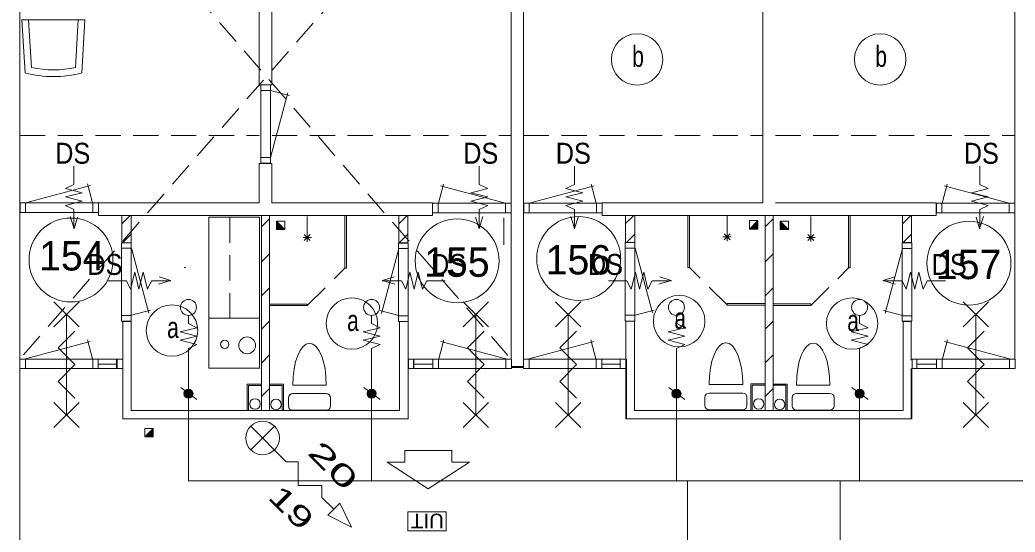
# Model space of a CAD drawing. Extents: x 295824 to 414724, y 24924 to 109024.
# Drawn here: x 302089 to 313944, y 70117 to 76222 of the extents above; entities that cross this region are included whole.
import ezdxf
from ezdxf.enums import TextEntityAlignment as Align

# ---------------------------------------------------------------- set-up
doc = ezdxf.new("R2010")
doc.units = 0
doc.header["$LTSCALE"] = 100
doc.linetypes.add('MEDIUM_DASHED', pattern=[4.5, 3, -1.5])
for name, color, linetype, lineweight in [('1', 7, 'Continuous', 13), ('16', 7, 'Continuous', 13), ('24', 7, 'Continuous', 13), ('61', 7, 'Continuous', 13)]:
    doc.layers.add(name, color=color, linetype=linetype, lineweight=lineweight)

msp = doc.modelspace()

# ---------------------------------------------------------------- hatches: boundary and pattern name
at = {"layer": '24'}
for points in [[(304151.5, 71768.1, 1), (304042.9, 71768.1, 1)], [(306333.5, 71768.1, 1), (306224.9, 71768.1, 1)], [(309964.5, 71768.1, 1), (309855.9, 71768.1, 1)], [(312146.5, 71768.1, 1), (312037.9, 71768.1, 1)]]:
    msp.add_hatch(color=256, dxfattribs=at).paths.add_polyline_path(points)
at = {"layer": '61'}
for points in [[(305244.4, 73722.8), (305144.4, 73822.8), (305144.4, 73722.8)], [(310781.4, 73729.4), (310881.4, 73829.4), (310881.4, 73729.4)], [(311243.8, 73724.1), (311143.8, 73824.1), (311143.8, 73724.1)], [(303578.3, 71252.8), (303678.3, 71352.8), (303678.3, 71252.8)]]:
    msp.add_hatch(color=256, dxfattribs=at).paths.add_polyline_path(points)

# ---------------------------------------------------------------- linework, layer by layer
at = {"layer": '1'}
for p, q in [((304097.2, 71736.8), (304097.2, 70726.3)), ((306279.2, 71730.1), (306279.2, 70726.3)), ((309910.2, 71736.8), (309910.2, 70726.3)), ((312092.2, 71730.1), (312092.2, 70726.3)), ((310043.5, 69843.4), (310043.5, 70726.3)), ((311859, 69838.4), (311859, 70726.3))]:
    msp.add_line(p, q, dxfattribs=at)
at = {"layer": '16'}
for p, q in [((302631.4, 74111.7), (302831.4, 74161.7)), ((307661.7, 74111.7), (307461.7, 74161.7)), ((308594.4, 74111.7), (308794.4, 74161.7)), ((313624.7, 74111.7), (313424.7, 74161.7)), ((303507.8, 73013.5), (303457.8, 73213.5)), ((306785.3, 73013.5), (306835.3, 73213.5)), ((309470.8, 73013.5), (309420.8, 73213.5)), ((312748.2, 73013.5), (312798.2, 73213.5))]:
    msp.add_line(p, q, dxfattribs=at)
at = {"layer": '24'}
for p, q in [((302734.8, 73736.3), (302689.8, 73880.4)), ((302777.2, 73872.1), (302734.8, 73736.3)), ((307515.9, 73872.1), (307558.3, 73736.3)), ((307558.3, 73736.3), (307603.3, 73880.4)), ((308697.7, 73736.3), (308652.7, 73880.4)), ((308740.2, 73872.1), (308697.7, 73736.3)), ((313478.9, 73872.1), (313521.3, 73736.3)), ((313521.3, 73736.3), (313566.3, 73880.4)), ((303747.4, 73159.3), (303883.2, 73116.9)), ((306545.7, 73159.3), (306409.9, 73116.9)), ((309710.4, 73159.3), (309846.2, 73116.9)), ((312508.6, 73159.3), (312372.8, 73116.9)), ((303883.2, 73116.9), (303739, 73071.9)), ((306409.9, 73116.9), (306554, 73071.9)), ((309846.2, 73116.9), (309702, 73071.9)), ((312372.8, 73116.9), (312517, 73071.9)), ((304097.2, 72253.5), (304097.2, 71714.1)), ((306279.2, 72253.5), (306279.2, 71745.1)), ((309910.2, 72253.5), (309910.2, 71714.1)), ((312092.2, 72253.5), (312092.2, 71745.1)), ((304005.6, 71838.9), (304197.1, 71697.3)), ((306187.6, 71838.9), (306379.1, 71697.3)), ((309818.6, 71838.9), (310010.2, 71697.3)), ((312000.6, 71838.9), (312192.1, 71697.3)), ((304097.2, 70726.3), (328693.9, 70726.3))]:
    msp.add_line(p, q, dxfattribs=at)
for points in [[(302831.4, 74161.7), (302631.4, 74211.7), (302731.4, 74261.7), (302731.4, 74480.4)], [(307461.7, 74161.7), (307661.7, 74211.7), (307561.7, 74261.7), (307561.7, 74480.4)], [(308794.4, 74161.7), (308594.4, 74211.7), (308694.4, 74261.7), (308694.4, 74480.4)], [(313424.7, 74161.7), (313624.7, 74211.7), (313524.7, 74261.7), (313524.7, 74480.4)], [(302731.4, 73730.4), (302731.4, 73961.7), (302631.4, 74011.7), (302831.4, 74061.7), (302631.4, 74111.7)], [(307561.7, 73730.4), (307561.7, 73961.7), (307661.7, 74011.7), (307461.7, 74061.7), (307661.7, 74111.7)], [(308694.4, 73730.4), (308694.4, 73961.7), (308594.4, 74011.7), (308794.4, 74061.7), (308594.4, 74111.7)], [(313524.7, 73730.4), (313524.7, 73961.7), (313624.7, 74011.7), (313424.7, 74061.7), (313624.7, 74111.7)], [(303457.8, 73213.5), (303407.8, 73013.5), (303357.8, 73113.5), (303139.1, 73113.5)], [(303889.1, 73113.5), (303657.8, 73113.5), (303607.8, 73013.5), (303557.8, 73213.5), (303507.8, 73013.5)], [(306404, 73113.5), (306635.3, 73113.5), (306685.3, 73013.5), (306735.3, 73213.5), (306785.3, 73013.5)], [(306835.3, 73213.5), (306885.3, 73013.5), (306935.3, 73113.5), (307154, 73113.5)], [(309420.8, 73213.5), (309370.8, 73013.5), (309320.8, 73113.5), (309102, 73113.5)], [(309852, 73113.5), (309620.8, 73113.5), (309570.8, 73013.5), (309520.8, 73213.5), (309470.8, 73013.5)], [(312367, 73113.5), (312598.2, 73113.5), (312648.2, 73013.5), (312698.2, 73213.5), (312748.2, 73013.5)], [(312798.2, 73213.5), (312848.2, 73013.5), (312898.2, 73113.5), (313117, 73113.5)], [(304097.2, 72703.5), (304097.2, 72603.5), (304197.2, 72553.5), (303997.2, 72503.5), (304197.2, 72453.5), (303997.2, 72403.5), (304197.2, 72353.5), (304097.2, 72303.5), (304097.2, 72253.5)], [(306279.2, 72703.5), (306279.2, 72603.5), (306379.2, 72553.5), (306179.2, 72503.5), (306379.2, 72453.5), (306179.2, 72403.5), (306379.2, 72353.5), (306279.2, 72303.5), (306279.2, 72253.5)], [(309910.2, 72703.5), (309910.2, 72603.5), (310010.2, 72553.5), (309810.2, 72503.5), (310010.2, 72453.5), (309810.2, 72403.5), (310010.2, 72353.5), (309910.2, 72303.5), (309910.2, 72253.5)], [(312092.2, 72703.5), (312092.2, 72603.5), (312192.2, 72553.5), (311992.2, 72503.5), (312192.2, 72453.5), (311992.2, 72403.5), (312192.2, 72353.5), (312092.2, 72303.5), (312092.2, 72253.5)]]:
    msp.add_lwpolyline(points, dxfattribs=at)
for centre, radius in [((304097.2, 72795.2), 95), ((306279.2, 72795.2), 95), ((309910.2, 72795.2), 95), ((312092.2, 72795.2), 95), ((304097.2, 71768.1), 54.3), ((306279.2, 71768.1), 54.3), ((309910.2, 71768.1), 54.3), ((312092.2, 71768.1), 54.3)]:
    msp.add_circle(centre, radius, dxfattribs=at)
at = {"layer": '61'}
for p, q in [((302090.1, 72179.9), (302090.1, 78890.8)), ((307940.1, 72179.6), (307940.1, 78890.8)), ((308090.1, 72179.8), (308090.1, 78890.8)), ((313940.1, 72179.8), (313940.1, 78890.8)), ((304940.1, 76611.3), (304940.1, 75450.1)), ((305090.1, 76626), (305090.1, 75450.1)), ((302227, 75655.3), (302193.6, 76221.1)), ((302783.3, 76221.1), (302751.8, 75655.2)), ((302863.4, 76221.1), (302828.4, 75591.8)), ((305090.1, 75450.1), (304940.1, 75450.1)), ((304959, 75449.3), (305073, 75449.3)), ((304959, 75382.3), (305073, 75382.3)), ((305073.6, 74581.5), (305280.6, 75354.2)), ((305074.2, 75379.9), (305301.1, 75319.2)), ((304959, 74582.3), (305073, 74582.3)), ((304940.1, 74510.2), (305090.1, 74510.2)), ((304940.1, 74510.2), (304940.1, 74040.8)), ((305090.1, 74510.2), (305090.1, 74040.8)), ((302156.8, 74041.6), (302929.6, 74248.6)), ((302955.2, 74042.2), (302894.5, 74269)), ((307075, 74038.5), (307135.8, 74265.4)), ((307873.4, 74037.9), (307100.7, 74244.9)), ((308156.5, 74036.8), (308929.3, 74243.8)), ((308955, 74037.4), (308894.2, 74264.3)), ((313075.3, 74038.5), (313136.1, 74265.4)), ((313873.7, 74037.9), (313101, 74244.9)), ((302157.6, 73926.9), (302157.6, 74040.9)), ((302957.6, 73926.9), (302957.6, 74040.9)), ((303024.6, 73926.9), (303024.6, 74040.9)), ((304940.1, 74040.8), (303025.4, 74040.8)), ((303025.4, 74040.8), (303025.4, 73890.8)), ((305090.1, 74040.8), (307004.9, 74040.8)), ((307004.9, 74040.8), (307004.9, 73890.8)), ((307005.7, 73923.2), (307005.7, 74037.2)), ((307072.7, 73923.2), (307072.7, 74037.2)), ((307872.7, 73923.2), (307872.7, 74037.2)), ((308157.3, 73922.2), (308157.3, 74036.2)), ((308957.3, 73922.2), (308957.3, 74036.2)), ((309024.3, 73922.2), (309024.3, 74036.2)), ((311090.1, 74040.8), (313005.2, 74040.8)), ((313005.2, 74040.8), (313005.2, 73890.8)), ((313006, 73923.2), (313006, 74037.2)), ((313073, 73923.2), (313073, 74037.2)), ((313873, 73923.2), (313873, 74037.2)), ((303025.4, 73890.8), (303315.1, 73890.8)), ((307004.9, 73890.8), (303025.4, 73890.8)), ((303301.8, 73789.9), (303401.5, 73889.6)), ((303303.2, 73566.1), (303303.2, 73890.2)), ((303303.2, 73890.2), (303413.2, 73890.2)), ((303413.2, 73566.1), (303413.2, 73890.2)), ((304941.8, 72071.6), (304941.8, 73872.2)), ((304966.4, 73890.8), (304966.4, 71565.8)), ((305062.7, 73890.8), (305062.7, 71565.8)), ((305512, 73678.6), (305512, 73878.6)), ((305961.9, 73885.1), (305961.9, 73264.6)), ((306602.2, 73566.1), (306602.2, 73890.2)), ((306602.2, 73890.2), (306712.2, 73890.2)), ((306603.9, 73789.9), (306703.6, 73889.6)), ((306605.9, 73892.1), (306719.9, 73892.1)), ((306712.2, 73566.1), (306712.2, 73890.2)), ((307854.9, 73539.4), (307854.9, 73863.5)), ((309301.2, 73791.1), (309400.9, 73890.8)), ((309302.7, 73567.3), (309302.7, 73891.4)), ((309302.7, 73891.4), (309412.6, 73891.4)), ((309412.6, 73567.3), (309412.6, 73891.4)), ((310063.9, 73891.7), (310063.9, 73271.2)), ((310513.7, 73685.2), (310513.7, 73885.2)), ((310965.8, 73892), (310965.8, 71567)), ((311062.1, 73892), (311062.1, 71567)), ((311511.5, 73679.9), (311511.5, 73879.9)), ((311961.3, 73886.4), (311961.3, 73265.9)), ((312601.6, 73567.3), (312601.6, 73891.4)), ((312601.6, 73891.4), (312711.6, 73891.4)), ((312603.3, 73791.1), (312703, 73890.8)), ((312711.6, 73567.3), (312711.6, 73891.4)), ((304966.9, 73754.6), (305062.7, 73850.4)), ((310966.3, 73755.8), (311062.1, 73851.6)), ((303314.1, 73567.3), (303413.8, 73667)), ((305462, 73628.6), (305562, 73628.6)), ((305476.7, 73664), (305547.4, 73593.3)), ((305476.7, 73593.3), (305547.4, 73664)), ((305512, 73678.6), (305512, 73578.6)), ((306612.5, 73567.3), (306712.2, 73667)), ((309313.5, 73568.5), (309413.2, 73668.2)), ((310563.7, 73635.2), (310463.7, 73635.2)), ((310549.1, 73670.6), (310478.4, 73599.9)), ((310549.1, 73599.9), (310478.4, 73670.6)), ((310513.7, 73685.2), (310513.7, 73585.2)), ((311461.5, 73629.9), (311561.5, 73629.9)), ((311476.1, 73665.2), (311546.8, 73594.5)), ((311476.1, 73594.5), (311546.8, 73665.2)), ((311511.5, 73679.9), (311511.5, 73579.9)), ((312611.9, 73568.5), (312711.6, 73668.2)), ((303303.2, 73566.1), (303413.2, 73566.1)), ((303418.6, 73500.6), (303625.7, 72727.8)), ((306601.5, 73562.6), (306715.5, 73562.6)), ((306602.2, 73566.1), (306712.2, 73566.1)), ((306714.9, 73562.6), (306714.9, 72628.6)), ((309300.9, 73566.5), (309300.9, 72634)), ((309300.9, 73501), (309414.9, 73501)), ((309302.7, 73567.3), (309412.6, 73567.3)), ((309418, 73501.8), (309625.1, 72729.1)), ((312600.9, 73563.8), (312714.9, 73563.8)), ((312601.6, 73567.3), (312711.6, 73567.3)), ((312714.3, 73563.8), (312714.3, 72629.8)), ((303301.5, 73499.8), (303415.5, 73499.8)), ((304966.9, 73336.5), (305062.7, 73432.3)), ((306602.9, 73496.3), (306395.8, 72723.6)), ((306714.9, 73495.6), (306600.9, 73495.6)), ((310966.3, 73337.7), (311062.1, 73433.5)), ((312602.3, 73497.6), (312395.2, 72724.8)), ((312714.3, 73496.8), (312600.3, 73496.8)), ((304046.5, 73270), (304064.5, 73270)), ((304966.9, 72931.9), (305062.7, 73027.7)), ((310966.3, 72933.1), (311062.1, 73028.9)), ((306715.1, 72958.1), (306715.1, 72065.8)), ((302794.8, 72863), (302494.8, 72563)), ((302494.8, 72863), (302794.8, 72563)), ((305061.5, 72817.1), (305511, 72817.1)), ((305061.9, 72835.1), (305511, 72835.1)), ((305511, 72817.1), (305511, 72835.1)), ((307670.3, 72863), (307370.3, 72563)), ((307370.3, 72863), (307670.3, 72563)), ((308771.2, 72863), (308471.2, 72563)), ((308471.2, 72863), (308771.2, 72563)), ((310963.9, 72841.7), (310514.8, 72841.7)), ((310514.8, 72823.7), (310514.8, 72841.7)), ((310964.2, 72823.7), (310514.8, 72823.7)), ((311060.9, 72818.4), (311510.4, 72818.4)), ((311061.3, 72836.4), (311510.4, 72836.4)), ((311510.4, 72818.4), (311510.4, 72836.4)), ((313627, 72863), (313327, 72563)), ((313327, 72863), (313627, 72563)), ((302644.8, 71513), (302644.8, 72713)), ((303301.5, 72699.8), (303415.5, 72699.8)), ((303419.3, 72702.2), (303646.1, 72762.9)), ((306602.2, 72697.9), (306375.4, 72758.7)), ((306714.9, 72695.6), (306600.9, 72695.6)), ((307520.3, 71513), (307520.3, 72713)), ((308621.2, 71513), (308621.2, 72713)), ((309300.9, 72701), (309414.9, 72701)), ((309418.7, 72703.4), (309645.5, 72764.2)), ((312601.6, 72699.1), (312374.8, 72759.9)), ((312714.3, 72696.8), (312600.3, 72696.8)), ((313477, 71513), (313477, 72713)), ((303307.4, 72629.2), (303412.7, 72629.2)), ((303315.1, 72631.2), (303315.1, 72180.6)), ((304342, 72666.3), (304939.4, 72666.3)), ((304966.9, 72535.9), (305062.7, 72631.7)), ((306612.7, 72627.8), (306612.7, 71565.8)), ((306612.7, 72627.8), (306707.4, 72627.8)), ((309306.8, 72630.4), (309306.8, 72064.6)), ((309306.8, 72630.4), (309412.1, 72630.4)), ((310966.3, 72537.2), (311062.1, 72632.9)), ((312612.1, 72629), (312612.1, 71567)), ((312612.1, 72629), (312706.8, 72629)), ((312706.8, 72629), (312706.8, 72167)), ((302155.5, 72180.4), (302928.2, 72387.5)), ((302953.9, 72181), (302893.2, 72407.9)), ((307078.8, 72181.1), (307139.5, 72407.9)), ((307877.2, 72180.4), (307104.4, 72387.5)), ((308153.2, 72180.4), (308925.9, 72387.5)), ((308951.6, 72181), (308890.8, 72407.9)), ((313078.9, 72181.1), (313139.7, 72407.9)), ((313877.3, 72180.4), (313104.6, 72387.5)), ((304966.9, 72132.6), (305062.7, 72228.3)), ((310966.3, 72133.8), (311062.1, 72229.6)), ((302156.3, 72065.8), (302156.3, 72179.8)), ((302956.3, 72065.8), (302956.3, 72179.8)), ((303023.3, 72065.8), (303023.3, 72179.8)), ((303249.3, 72119.9), (303023.3, 72119.9)), ((303239.2, 72065.8), (303239.2, 72179.8)), ((303249.3, 72065.8), (303249.3, 72179.8)), ((306775.9, 72065.8), (306775.9, 72179.8)), ((306783.4, 72065.8), (306783.4, 72179.8)), ((306783.4, 72119.9), (307009.4, 72119.9)), ((307009.4, 72065.8), (307009.4, 72179.8)), ((307076.4, 72065.8), (307076.4, 72179.8)), ((307876.4, 72065.8), (307876.4, 72179.8)), ((307944.7, 72092.1), (308085.9, 72092.1)), ((308153.9, 72065.8), (308153.9, 72179.8)), ((308953.9, 72065.8), (308953.9, 72179.8)), ((309020.9, 72065.8), (309020.9, 72179.8)), ((309246.9, 72119.9), (309020.9, 72119.9)), ((309238.6, 72067), (309238.6, 72181)), ((312775.3, 72067), (312775.3, 72181)), ((312783.6, 72119.9), (313009.6, 72119.9)), ((313009.6, 72065.8), (313009.6, 72179.8)), ((313076.6, 72065.8), (313076.6, 72179.8)), ((313876.6, 72065.8), (313876.6, 72179.8)), ((302090.1, 69301.2), (302090.1, 72065.2)), ((304341.8, 72071.6), (304941.8, 72071.6)), ((307944.7, 72077.1), (308085.9, 72077.1)), ((304812.6, 71866.2), (304962.6, 71866.2)), ((304812.6, 71566.2), (304812.6, 71866.2)), ((305062.7, 71865.8), (305212.7, 71865.8)), ((305212.7, 71865.8), (305212.7, 71565.8)), ((305739.5, 71868.7), (305339.5, 71868.7)), ((310699.5, 71874.9), (310299.5, 71874.9)), ((310812, 71867.4), (310962, 71867.4)), ((310812, 71567.4), (310812, 71867.4)), ((311062.1, 71867), (311212.1, 71867)), ((311212.1, 71867), (311212.1, 71567)), ((311738.9, 71869.9), (311338.9, 71869.9)), ((304966.9, 71731.7), (305062.7, 71827.4)), ((305339.5, 71768.7), (305739.5, 71768.7)), ((310249.5, 71624.9), (310249.5, 71724.9)), ((310299.5, 71774.9), (310699.5, 71774.9)), ((310749.5, 71724.9), (310749.5, 71624.9)), ((310966.3, 71732.9), (311062.1, 71828.7)), ((311338.9, 71769.9), (311738.9, 71769.9)), ((302794.8, 71663), (302494.8, 71363)), ((302494.8, 71663), (302794.8, 71363)), ((305289.5, 71618.7), (305289.5, 71718.7)), ((305789.5, 71718.7), (305789.5, 71618.7)), ((307670.3, 71663), (307370.3, 71363)), ((307370.3, 71663), (307670.3, 71363)), ((308771.2, 71663), (308471.2, 71363)), ((308471.2, 71663), (308771.2, 71363)), ((311288.9, 71619.9), (311288.9, 71719.9)), ((311788.9, 71719.9), (311788.9, 71619.9)), ((313627, 71663), (313327, 71363)), ((313327, 71663), (313627, 71363)), ((305739.5, 71568.7), (305339.5, 71568.7)), ((310699.5, 71574.9), (310299.5, 71574.9)), ((311738.9, 71569.9), (311338.9, 71569.9)), ((305121.4, 71379.7), (304838.6, 71096.9))]:
    msp.add_line(p, q, dxfattribs=at)
at = {"layer": '61', "linetype": 'MEDIUM_DASHED'}
for p, q in [((302112.4, 78915.1), (307930.8, 72187.9)), ((307950.5, 78895.5), (302112.4, 72207.6)), ((302090.1, 74844.1), (304939.8, 74844.1)), ((305093, 74844.1), (307940.7, 74844.1)), ((308091.8, 74844.1), (310940.1, 74844.1)), ((311090.6, 74844.1), (313940.8, 74844.1)), ((304588.3, 72666.3), (304588.3, 73873.6)), ((305513.1, 72817.6), (305960, 73264.5)), ((310512.7, 72824.1), (310065.8, 73271)), ((311512.5, 72818.8), (311959.4, 73265.7))]:
    msp.add_line(p, q, dxfattribs=at)
at = {"layer": '61'}
for points in [[(310940.1, 79104.8), (310940.1, 74040.8), (309025.1, 74040.8), (309025.1, 73890.8), (313005.2, 73890.8)], [(302150.7, 75591.9), (302113.4, 76221.1), (302863.4, 76221.1)], [(304959, 74515.3), (305073, 74515.3), (305073, 75449.3)], [(304959, 75449.3), (304959, 74515.3), (305073, 74515.3)], [(302090.6, 73926.9), (302090.6, 74040.9), (303024.6, 74040.9)], [(303024.6, 73926.9), (302090.6, 73926.9), (302090.6, 74040.9)], [(307939.7, 73923.2), (307939.7, 74037.2), (307005.7, 74037.2)], [(307005.7, 73923.2), (307939.7, 73923.2), (307939.7, 74037.2)], [(308090.3, 73922.2), (308090.3, 74036.2), (309024.3, 74036.2)], [(309024.3, 73922.2), (308090.3, 73922.2), (308090.3, 74036.2)], [(313940, 73923.2), (313940, 74037.2), (313006, 74037.2)], [(313006, 73923.2), (313940, 73923.2), (313940, 74037.2)], [(304341.8, 72071.6), (304341.8, 73872.2), (304941.8, 73872.2)], [(305979.9, 73885.1), (305979.9, 73264.6), (305961.9, 73264.6)], [(310045.9, 73891.7), (310045.9, 73271.2), (310063.9, 73271.2)], [(311979.3, 73886.4), (311979.3, 73265.9), (311961.3, 73265.9)], [(305144.4, 73822.8), (305144.4, 73722.8), (305244.4, 73722.8)], [(310881.4, 73829.4), (310881.4, 73729.4), (310781.4, 73729.4)], [(311143.8, 73824.1), (311143.8, 73724.1), (311243.8, 73724.1)], [(303412.7, 72629.2), (303412.7, 71565.8), (306612.7, 71565.8)], [(309412.1, 72630.4), (309412.1, 71567), (312612.1, 71567)], [(302744.8, 71713), (302544.8, 71913), (302744.8, 72113), (302544.8, 72313), (302744.8, 72513)], [(307620.3, 71713), (307420.3, 71913), (307620.3, 72113), (307420.3, 72313), (307620.3, 72513)], [(308721.2, 71713), (308521.2, 71913), (308721.2, 72113), (308521.2, 72313), (308721.2, 72513)], [(313577, 71713), (313377, 71913), (313577, 72113), (313377, 72313), (313577, 72513)], [(303315.1, 72065.2), (303315.1, 71465.8), (306715.1, 71465.8), (306715.1, 72065.8)], [(309306.8, 72067), (309306.8, 71467), (312706.8, 71467), (312706.8, 72067)], [(309315.1, 72065.8), (309315.1, 71465.8), (312715.1, 71465.8), (312715.1, 72065.8)], [(304797.6, 71566.2), (304797.6, 71881.2), (304962.6, 71881.2)], [(305062.7, 71880.8), (305227.7, 71880.8), (305227.7, 71565.8)], [(310797, 71567.4), (310797, 71882.4), (310962, 71882.4)], [(311062.1, 71882), (311227.1, 71882), (311227.1, 71567)], [(304838.6, 71379.7), (305262.9, 70955.5), (305404.3, 70955.5), (305404.3, 70672.6), (305687.1, 70672.6), (305687.1, 70531.2), (305828.5, 70389.8)], [(303678.3, 71352.8), (303678.3, 71252.8), (303578.3, 71252.8)]]:
    msp.add_lwpolyline(points, dxfattribs=at)
for points in [[(305144.4, 73822.8), (305244.4, 73822.8), (305244.4, 73722.8)], [(305244.4, 73722.8), (305144.4, 73822.8), (305144.4, 73722.8)], [(310881.4, 73829.4), (310781.4, 73829.4), (310781.4, 73729.4)], [(310781.4, 73729.4), (310881.4, 73829.4), (310881.4, 73729.4)], [(311143.8, 73824.1), (311243.8, 73824.1), (311243.8, 73724.1)], [(311243.8, 73724.1), (311143.8, 73824.1), (311143.8, 73724.1)], [(303301.5, 72631.9), (303415.5, 72631.9), (303415.5, 73565.9), (303301.5, 73565.9)], [(306714.9, 73562.6), (306714.9, 72628.6), (306600.9, 72628.6), (306600.9, 73562.6)], [(309300.9, 72633.1), (309414.9, 72633.1), (309414.9, 73567.1), (309300.9, 73567.1)], [(312714.3, 73563.8), (312714.3, 72629.8), (312600.3, 72629.8), (312600.3, 73563.8)], [(302089.3, 72065.8), (302089.3, 72179.8), (303315.7, 72179.8), (303315.7, 72065.8)], [(302089.3, 72065.8), (302089.3, 72179.8), (303315.7, 72179.8), (303315.7, 72065.8)], [(306716.4, 72065.8), (306716.4, 72179.8), (307943.4, 72179.8), (307943.4, 72065.8)], [(308086.9, 72065.8), (308086.9, 72179.8), (309313.3, 72179.8), (309313.3, 72065.8)], [(308086.9, 72065.8), (308086.9, 72179.8), (309313.3, 72179.8), (309313.3, 72065.8)], [(312716.6, 72065.8), (312716.6, 72179.8), (313943.6, 72179.8), (313943.6, 72065.8)], [(303678.3, 71352.8), (303578.3, 71352.8), (303578.3, 71252.8)], [(303578.3, 71252.8), (303678.3, 71352.8), (303678.3, 71252.8)], [(306673.7, 71089.3), (307233.7, 71089.3), (307233.7, 70949.3), (307443.7, 70949.3), (306953.7, 70634.3), (306463.7, 70949.3), (306673.7, 70949.3)], [(305757.8, 70319.1), (305899.3, 70460.5), (306040.7, 70177.6)], [(307168, 70358.2), (306708.4, 70358.2), (306708.4, 70133.6), (307168, 70133.6)]]:
    msp.add_lwpolyline(points, close=True, dxfattribs=at)
for centre, radius in [((309441.3, 75751.7), 306.3), ((312336.8, 75751.7), 306.3), ((302697.7, 73360.8), 500), ((308745.1, 73377.9), 500), ((307297.3, 73350.1), 500), ((313394.5, 73322.2), 500), ((306044.7, 72603.3), 306.3), ((309942.5, 72631.2), 306.3), ((312002.7, 72603.3), 306.3), ((303900.9, 72519.7), 306.3), ((304796.8, 72342.8), 100), ((304528.9, 72355.1), 50), ((304890.2, 71643.7), 62.5), ((305140.2, 71638.2), 62.5), ((310889.6, 71644.9), 62.5), ((311139.5, 71639.4), 62.5), ((304980, 71238.3), 200)]:
    msp.add_circle(centre, radius, dxfattribs=at)
for centre, radius, start, end in [((302489.6, 76831.5), 1205.2, 257.41626, 282.56606), ((302489.6, 76831.5), 1285.2, 254.70731, 285.28507), ((305339.5, 71718.7), 50, 90, 180), ((305739.5, 71718.7), 50, 0, 90), ((310299.5, 71724.9), 50, 90, 180), ((310699.5, 71724.9), 50, 0, 90), ((311338.9, 71720), 50, 90, 180), ((311738.9, 71720), 50, 0, 90), ((305339.5, 71618.7), 50, 180, 270), ((305739.5, 71618.7), 50, 270, 0), ((310299.5, 71624.9), 50, 180, 270), ((310699.5, 71624.9), 50, 270, 0), ((311338.9, 71620), 50, 180, 270), ((311738.9, 71620), 50, 270, 0)]:
    msp.add_arc(centre, radius, start, end, dxfattribs=at)
for centre in [(305539.5, 71868.7), (310499.5, 71874.9), (311538.9, 71870)]:
    msp.add_ellipse(centre, major_axis=(0, 500), ratio=0.4, start_param=4.712389, end_param=7.8539816, dxfattribs=at)

# ---------------------------------------------------------------- texts
at = {"layer": '24', "width": 0.9}
for p in [(302509.6, 74507.5), (307370.2, 74507.5), (308472.5, 74507.5), (313333.1, 74507.5), (302892.7, 73182.5), (306987.1, 73182.5), (308855.6, 73182.5), (312950, 73182.5)]:
    msp.add_text('DS', height=250, dxfattribs=at).set_placement(p)
at = {"layer": '61', "width": 0.75}
for s, p in [('b', (309383.3, 75662.5)), ('b', (312278.8, 75662.5)), ('a', (305986.7, 72514.1)), ('a', (309884.5, 72542)), ('a', (311944.7, 72514.1)), ('a', (303842.9, 72430.6))]:
    msp.add_text(s, height=250, dxfattribs=at).set_placement(p)
at = {"layer": '61'}
for s, p in [('154', (302708, 73235.3)), ('155', (307294.4, 73160.2)), ('156', (308742.1, 73188.1)), ('157', (313390.2, 73132.3))]:
    msp.add_text(s, height=350, dxfattribs=at).set_placement(p, align=Align.CENTER)
for s, height, rotation, width, p in [('20', 250, 315, 1.75, (305502.6, 71053.1)), ('19', 250, 315, 1.55, (305030.3, 70524.6)), ('UIT', 175, 180, 1.05, (307141.3, 70336.8))]:
    msp.add_text(s, height=height, rotation=rotation, dxfattribs=dict(at, width=width)).set_placement(p)

doc.saveas('drawing.dxf')
